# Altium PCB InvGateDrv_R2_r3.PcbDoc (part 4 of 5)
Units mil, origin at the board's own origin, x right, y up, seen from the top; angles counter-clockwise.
Board outline 6245 x 2850 mil, 4 copper layers (Top Layer, Power, Ground, Bottom Layer), stack 104.204 mil thick; 409 components, 181 nets, 1050 pads, 683 vias.
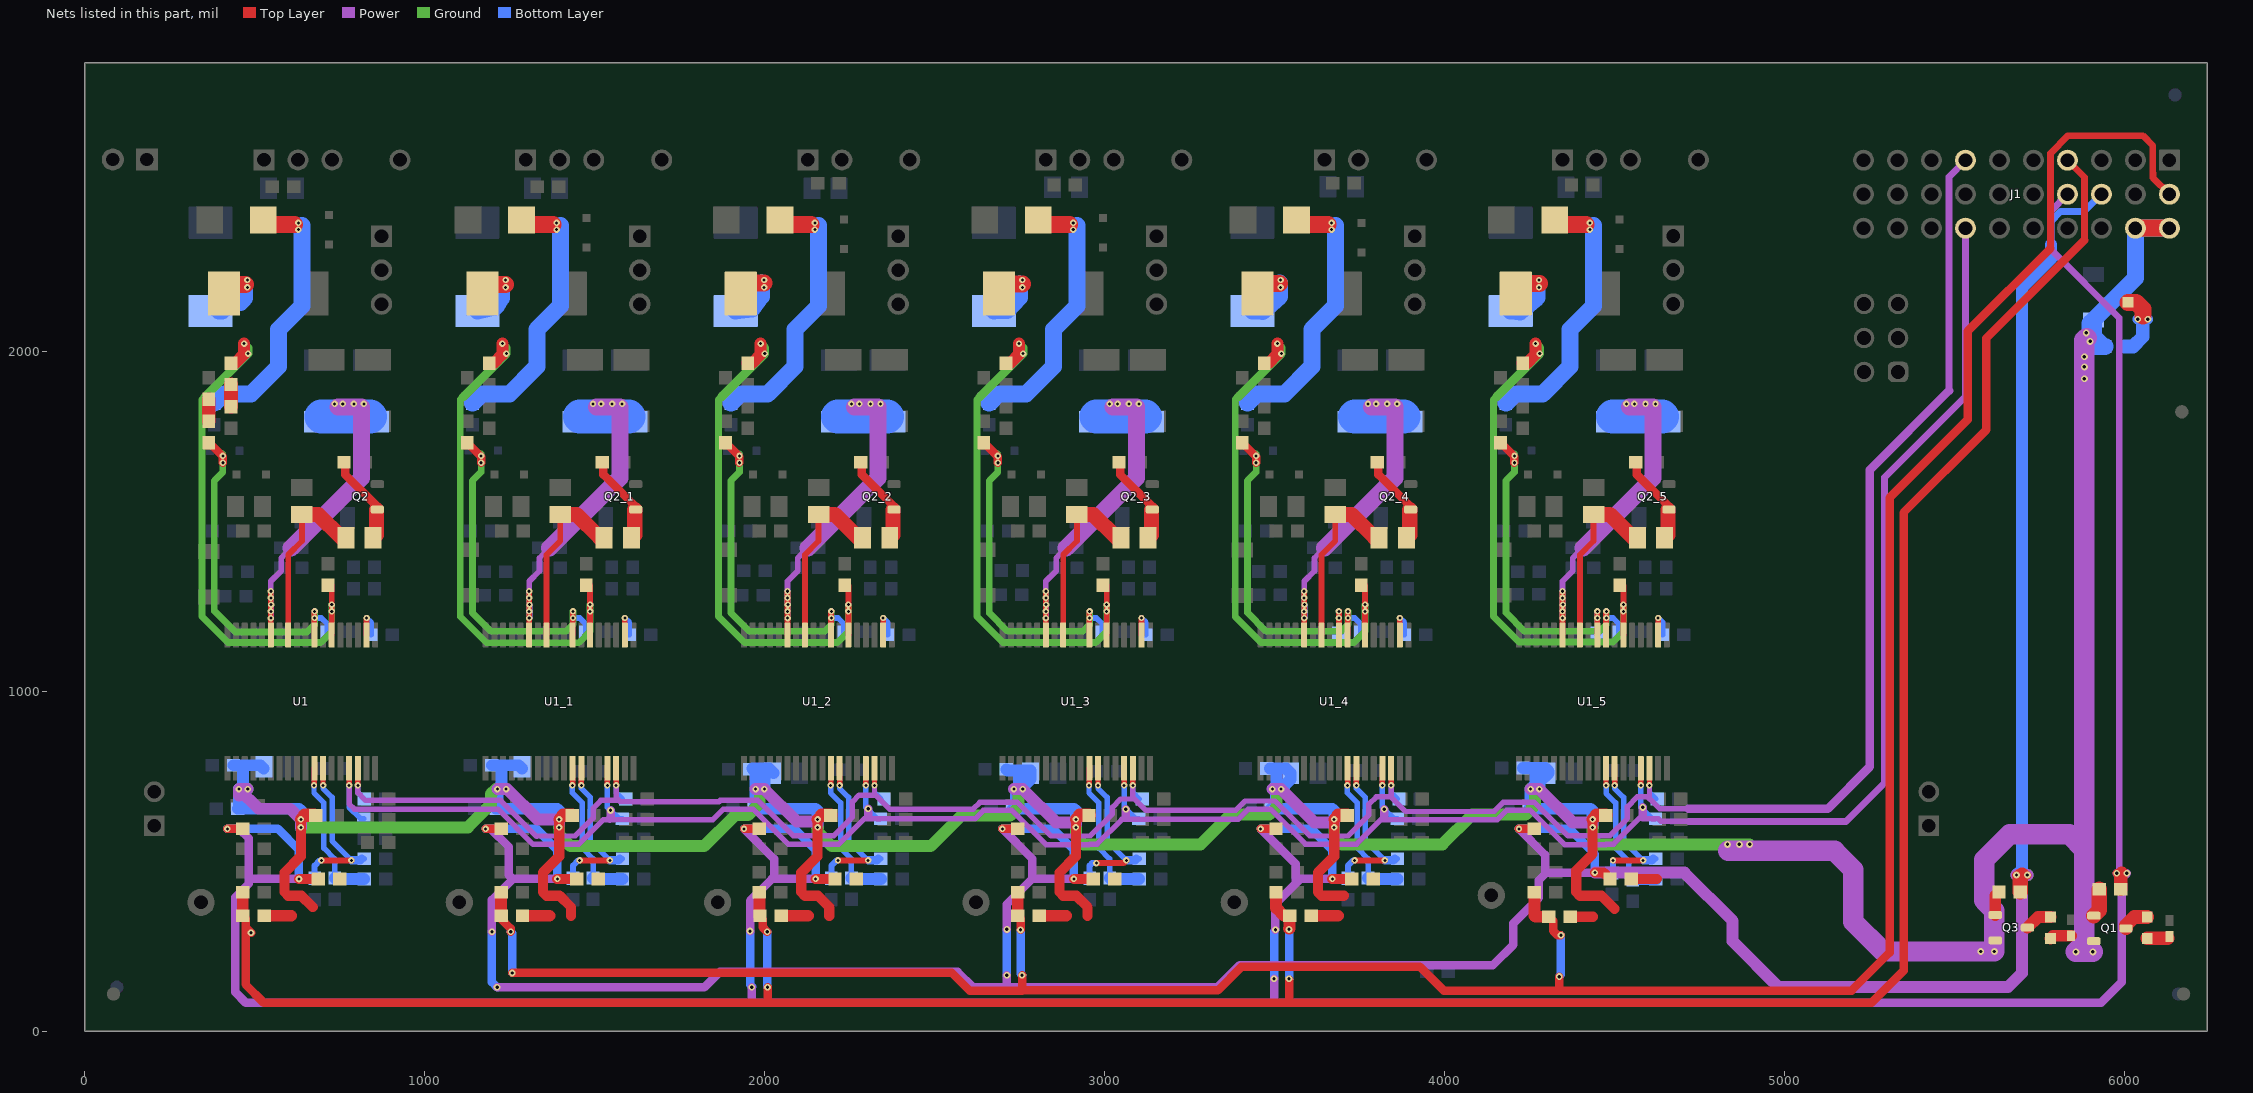
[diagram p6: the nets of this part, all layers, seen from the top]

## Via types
v1: diameter 19, hole 9, Top Layer to Bottom Layer, tented both sides, 617 vias
v2: diameter 20, hole 10, Top Layer to Bottom Layer, tented both sides, 66 vias

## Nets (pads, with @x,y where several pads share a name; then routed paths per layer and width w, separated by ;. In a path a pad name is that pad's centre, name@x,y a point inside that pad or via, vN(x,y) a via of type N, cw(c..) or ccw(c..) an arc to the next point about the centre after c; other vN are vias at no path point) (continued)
NetC17_4_1: C17_4.1 U1_4.27 | length 174.7
  Top Layer w17: U1_4.27@3690.16,1165.91 v1(3690.16,1235.79)
  Power w17: v1(3690.16,1216.1) v1(3690.16,1235.79)
  Ground w17: v1(3690.16,1216.1) v1(3690.16,1235.79)
  Bottom Layer w17: v1(3690.16,1235.79) v1(3690.16,1216.1) 3690.16,1178.7 C17_4.1@3696.06,1172.79
NetC17_5_1: C17_5.1 U1_5.27 | length 174.7
  Top Layer w17: U1_5.27@4450.15,1165.91 v1(4450.15,1216.11) v1(4450.15,1235.79)
  Power w17: v1(4450.15,1216.11) v1(4450.15,1235.79)
  Ground w17: v1(4450.15,1216.11) v1(4450.15,1235.79)
  Bottom Layer w17: v1(4450.15,1235.79) v1(4450.15,1216.11) 4450.15,1178.71 C17_5.1@4456.06,1172.8
NetC18_1: C18.1 R18.1 U1.26 | length 1077.1
  Top Layer w17: U1.26@675.75,1165.91 675.75,1234.8 v1(676.73,1235.79)
  Top Layer w25: R18.1@365.39,1732.09 406.57,1690.91 v1(406.57,1672.89)
  Ground w20: v1@406.57,1698.39 v1(406.57,1692.81) v1(406.57,1672.89) 406.57,1645.15 381.46,1620.03 381.46,1236.75 443.2,1175 654.33,1175 676.73,1197.4 v1(676.73,1216.1) v1(676.73,1235.79)
  Bottom Layer w17: v1(676.73,1235.79) v1(676.73,1216.1) 696.42,1216.1 714.13,1198.39 C18.1@714.13,1175.86 C18.1@714.13,1172.8
NetC18_1_1: C18_1.1 R18_1.1 U1_1.26 | length 1079.1
  Top Layer w17: U1_1.26@1435.74,1165.91 1435.74,1234.81 v1(1436.73,1235.79)
  Top Layer w25: R18_1.1@1125.39,1732.09 1166.57,1690.91 v1(1166.57,1672.89)
  Ground w20: v1@1166.57,1698.39 v1(1166.57,1692.81) v1(1166.57,1672.89) 1166.57,1645.15 1141.45,1620.04 1141.45,1230.49 1194.89,1177.05 1416.37,1177.05 1436.73,1197.4 v1(1436.73,1216.1) v1(1436.73,1235.79)
  Bottom Layer w17: v1(1436.73,1235.79) v1(1436.73,1216.1) 1456.41,1216.1 1474.13,1198.39 C18_1.1@1474.13,1175.87 C18_1.1@1474.13,1172.8
NetC18_2_1: C18_2.1 R18_2.1 U1_2.26 | length 1078.8
  Top Layer w17: U1_2.26@2195.75,1165.91 2195.75,1234.8 v1(2196.73,1235.79)
  Top Layer w25: R18_2.1@1885.39,1732.09 1926.57,1690.91 v1(1926.57,1672.89)
  Ground w20: v1@1926.57,1698.39 v1(1926.57,1692.81) v1(1926.57,1672.89) 1926.57,1645.15 1901.46,1620.03 1901.46,1230.94 1955.35,1177.05 2176.38,1177.05 2196.73,1197.4 v1(2196.73,1216.1) v1(2196.73,1235.79)
  Bottom Layer w17: v1(2196.73,1235.79) v1(2196.73,1216.1) 2216.42,1216.1 2234.13,1198.39 C18_2.1@2234.13,1175.86 C18_2.1@2234.13,1172.79
NetC18_3_1: C18_3.1 R18_3.1 U1_3.26 | length 1078.7
  Top Layer w17: U1_3.26@2955.75,1165.91 2955.75,1234.8 v1(2956.73,1235.79)
  Top Layer w25: R18_3.1@2645.39,1732.09 2686.57,1690.91 v1(2686.57,1672.89)
  Ground w20: v1@2686.57,1698.39 v1(2686.57,1692.81) v1(2686.57,1672.89) 2686.57,1645.15 2661.46,1620.03 2661.46,1231.08 2715.49,1177.05 2936.38,1177.05 2956.73,1197.4 v1(2956.73,1216.1) v1(2956.73,1235.79)
  Bottom Layer w17: v1(2956.73,1235.79) v1(2956.73,1216.1) 2976.42,1216.1 2994.13,1198.39 C18_3.1@2994.13,1175.86 C18_3.1@2994.13,1172.8
NetC18_4_1: C18_4.1 R18_4.1 U1_4.26 | length 1078.3
  Top Layer w17: U1_4.26@3715.75,1165.91 3715.75,1234.8 v1(3716.73,1235.79)
  Top Layer w25: R18_4.1@3405.39,1732.09 3446.57,1690.91 v1(3446.57,1672.89)
  Ground w20: v1@3446.57,1698.39 v1(3446.57,1692.81) v1(3446.57,1672.89) 3446.57,1645.15 3421.46,1620.03 3421.46,1231.77 3476.18,1177.05 3696.38,1177.05 3716.73,1197.4 v1(3716.73,1216.1) v1(3716.73,1235.79)
  Bottom Layer w17: v1(3716.73,1235.79) v1(3716.73,1216.1) 3736.42,1216.1 3754.13,1198.39 C18_4.1@3754.13,1175.86 C18_4.1@3754.13,1172.79
NetC18_5_1: C18_5.1 R18_5.1 U1_5.26 | length 1078.3
  Top Layer w17: U1_5.26@4475.74,1165.91 4475.74,1234.81 v1(4476.73,1235.79)
  Top Layer w25: R18_5.1@4165.39,1732.09 4206.57,1690.91 v1(4206.57,1672.89)
  Ground w20: v1@4206.57,1698.39 v1(4206.57,1692.81) v1(4206.57,1672.89) 4206.57,1645.16 4181.45,1620.04 4181.45,1231.77 4236.17,1177.05 4456.38,1177.05 4476.73,1197.41 v1(4476.73,1216.11) v1(4476.73,1235.79)
  Bottom Layer w17: v1(4476.73,1235.79) v1(4476.73,1216.11) 4496.41,1216.11 4514.13,1198.39 C18_5.1@4514.13,1175.87 C18_5.1@4514.13,1172.8
NetC19_1: C19.1 R21.1 U1.24 | length 1598.3
  Top Layer w17: C19.1@725.94,1312.56 726.93,1311.57 v1(726.93,1255.47) v1(726.93,1235.79) U1.24@726.93,1165.91
  Top Layer w35: R21.1@430.51,1966.1 443.46,1966.1 468.9,1991.54 v1(468.9,2023.19)
  Ground w20: 352.91,1865.71 351.69,1865.71 345,1859.02 345,1220.4 421.15,1144.25 694.84,1144.25 726.93,1176.34 v1(726.93,1235.79) v1(726.93,1255.47)
  Ground w25: 352.91,1865.71 v1(480.87,1993.66) 480.87,2011.22 v1(468.9,2023.19)
NetC19_1_1: C19_1.1 R21_1.1 U1_1.24 | length 1599.1
  Top Layer w17: C19_1.1@1485.94,1312.56 1486.92,1311.58 v1(1486.92,1255.47) v1(1486.92,1235.79) U1_1.24@1486.92,1165.91
  Top Layer w35: R21_1.1@1190.51,1966.1 1203.46,1966.1 1228.89,1991.54 v1(1228.89,2023.19)
  Ground w20: 1112.91,1865.71 1111.69,1865.71 1105,1859.02 1105,1220.4 1182.13,1143.27 1453.85,1143.27 1486.92,1176.34 v1(1486.92,1235.79) v1(1486.92,1255.47)
  Ground w25: 1112.91,1865.71 v1(1240.86,1993.66) 1240.86,2011.22 v1(1228.89,2023.19)
NetC19_2_1: C19_2.1 R21_2.1 U1_2.24 | length 1598.3
  Top Layer w17: C19_2.1@2245.94,1312.56 2246.93,1311.57 v1(2246.93,1255.47) v1(2246.93,1235.79) U1_2.24@2246.93,1165.91
  Top Layer w35: R21_2.1@1950.51,1966.1 1963.46,1966.1 1988.9,1991.54 v1(1988.9,2023.19)
  Ground w20: 1872.91,1865.71 1871.69,1865.71 1865,1859.02 1865,1220.4 1941.15,1144.25 2214.84,1144.25 2246.93,1176.34 v1(2246.93,1235.79) v1(2246.93,1255.47)
  Ground w25: 1872.91,1865.71 v1(2000.87,1993.66) 2000.87,2011.22 v1(1988.9,2023.19)
NetC19_3_1: C19_3.1 R21_3.1 U1_3.24 | length 1598.3
  Top Layer w17: C19_3.1@3005.94,1312.56 3006.93,1311.57 v1(3006.93,1255.47) v1(3006.93,1235.79) U1_3.24@3006.93,1165.91
  Top Layer w35: R21_3.1@2710.51,1966.1 2723.46,1966.1 2748.9,1991.54 v1(2748.9,2023.19)
  Ground w20: 2632.91,1865.71 2631.69,1865.71 2625,1859.02 2625,1220.4 2701.15,1144.25 2974.84,1144.25 3006.93,1176.34 v1(3006.93,1235.79) v1(3006.93,1255.47)
  Ground w25: 2632.91,1865.71 v1(2760.87,1993.66) 2760.87,2011.22 v1(2748.9,2023.19)
NetC19_4_1: C19_4.1 R21_4.1 U1_4.24 | length 1598.3
  Top Layer w17: C19_4.1@3765.94,1312.56 3766.93,1311.57 v1(3766.93,1255.47) v1(3766.93,1235.79) U1_4.24@3766.93,1165.91
  Top Layer w35: R21_4.1@3470.51,1966.1 3483.46,1966.1 3508.9,1991.54 v1(3508.9,2023.19)
  Ground w20: 3392.91,1865.71 3391.69,1865.71 3385,1859.02 3385,1220.4 3461.15,1144.25 3734.84,1144.25 3766.93,1176.34 v1(3766.93,1235.79) v1(3766.93,1255.47)
  Ground w25: 3392.91,1865.71 v1(3520.87,1993.66) 3520.87,2011.22 v1(3508.9,2023.19)
NetC19_5_1: C19_5.1 R21_5.1 U1_5.24 | length 1597.2
  Top Layer w17: C19_5.1@4525.94,1312.56 4526.93,1311.58 v1(4526.93,1255.48) v1(4526.93,1235.79) U1_5.24@4526.93,1165.91
  Top Layer w35: R21_5.1@4230.51,1966.11 4243.46,1966.11 4268.89,1991.54 v1(4268.89,2023.19)
  Ground w20: 4152.91,1865.71 4151.69,1865.71 4145,1859.02 4145,1220.4 4219.87,1145.53 4496.12,1145.53 4526.93,1176.34 v1(4526.93,1235.79) v1(4526.93,1255.48)
  Ground w25: 4152.91,1865.71 v1(4280.86,1993.67) 4280.86,2011.23 v1(4268.89,2023.19)
NetC25_1: C25.1 R17.2 U1.11 | length 436.4
  Top Layer w16: v1(674.76,723.98) 675.75,724.96 U1.11@675.75,774.17
  Bottom Layer w16: v1(674.76,723.98) 674.76,701.34 704.04,672.06 704.04,539.19 735.79,507.44 R17.2@735.79,451.34
  Bottom Layer w35: R17.2@735.79,451.34 738.74,448.39 C25.1@822.4,448.39
NetC25_1_1: C25_1.1 R17_1.2 U1_1.11 | length 436.4
  Top Layer w16: v1(1434.76,723.98) 1435.74,724.96 U1_1.11@1435.74,774.18
  Bottom Layer w16: v1(1434.76,723.98) 1434.76,701.34 1464.04,672.07 1464.04,539.19 1495.78,507.44 R17_1.2@1495.78,451.34
  Bottom Layer w35: R17_1.2@1495.78,451.34 1498.74,448.39 C25_1.1@1582.4,448.39
NetC25_2_1: C25_2.1 R17_2.2 U1_2.11 | length 436.4
  Top Layer w16: v1(2194.76,723.98) 2195.75,724.96 U1_2.11@2195.75,774.17
  Bottom Layer w16: v1(2194.76,723.98) 2194.76,701.34 2224.04,672.06 2224.04,539.19 2255.79,507.44 R17_2.2@2255.79,451.34
  Bottom Layer w35: R17_2.2@2255.79,451.34 2258.74,448.39 C25_2.1@2342.4,448.39
NetC25_3_1: C25_3.1 R17_3.2 U1_3.11 | length 436.4
  Top Layer w16: v1(2954.76,723.98) 2955.75,724.96 U1_3.11@2955.75,774.17
  Bottom Layer w16: v1(2954.76,723.98) 2954.76,701.34 2984.04,672.06 2984.04,539.19 3015.79,507.44 R17_3.2@3015.79,451.34
  Bottom Layer w35: R17_3.2@3015.79,451.34 3018.74,448.39 C25_3.1@3102.4,448.39
NetC25_4_1: C25_4.1 R17_4.2 U1_4.11 | length 436.4
  Top Layer w16: v1(3714.76,723.98) 3715.75,724.96 U1_4.11@3715.75,774.17
  Bottom Layer w16: v1(3714.76,723.98) 3714.76,701.34 3744.04,672.06 3744.04,539.19 3775.79,507.44 R17_4.2@3775.79,451.34
  Bottom Layer w35: R17_4.2@3775.79,451.34 3778.74,448.39 C25_4.1@3862.4,448.39
NetC25_5_1: C25_5.1 R17_5.2 U1_5.11 | length 412.6
  Top Layer w16: U1_5.11@4475.74,774.18 4475.74,724.97 4476,724.71 v1(4476,724)
  Bottom Layer w16: v1(4476,724) 4476,700.1 4504.04,672.07 4504.04,539.19 4543.35,499.88 4543.35,462.62 R17_5.2@4553.35,452.62
  Bottom Layer w35: R17_5.2@4563.5,448.39 C25_5.1@4622.4,448.39
NetC26_1: C26.1 R19.2 U1.12 | length 496.8
  Top Layer w16: v1(701.34,723.98) U1.12@701.34,774.17
  Top Layer w18: v1(696.42,503.24) v1(785,503.24)
  Bottom Layer w16: v1(701.34,723.98) 701.34,714.82 727.91,688.24 727.91,560.32 v1(785,503.24) ; C26.1@814.53,507.44 C26.1@822.4,507.44
  Bottom Layer w18: R19.2@676.73,450.35 676.73,487.76 692.21,503.24 v1(696.42,503.24)
  Bottom Layer w25: v1(785,503.24) 810.32,503.24 C26.1@814.53,507.44
NetC26_1_1: C26_1.1 R19_1.2 U1_1.12 | length 496.8
  Top Layer w16: v1(1461.33,723.98) U1_1.12@1461.33,774.18
  Top Layer w18: v1(1456.41,503.24) v1(1545,503.24)
  Bottom Layer w16: v1(1461.33,723.98) 1461.33,714.82 1487.91,688.25 1487.91,560.32 v1(1545,503.24) ; C26_1.1@1574.52,507.44 C26_1.1@1582.4,507.44
  Bottom Layer w18: R19_1.2@1436.73,450.36 1436.73,487.76 1452.21,503.24 v1(1456.41,503.24)
  Bottom Layer w25: v1(1545,503.24) 1570.32,503.24 C26_1.1@1574.52,507.44
NetC26_2_1: C26_2.1 R19_2.2 U1_2.12 | length 496.8
  Top Layer w16: v1(2221.34,723.98) U1_2.12@2221.34,774.17
  Top Layer w18: v1(2216.42,503.24) v1(2305,503.24)
  Bottom Layer w16: v1(2221.34,723.98) 2221.34,714.82 2247.91,688.24 2247.91,560.32 v1(2305,503.24) ; C26_2.1@2334.53,507.44 C26_2.1@2342.4,507.44
  Bottom Layer w18: R19_2.2@2196.73,450.35 2196.73,487.76 2212.21,503.24 v1(2216.42,503.24)
  Bottom Layer w25: v1(2305,503.24) 2330.32,503.24 C26_2.1@2334.53,507.44
NetC26_3_1: C26_3.1 R19_3.2 U1_3.12 | length 497.2
  Top Layer w16: v1(2981.34,723.98) U1_3.12@2981.34,774.17
  Top Layer w18: v1(2976.42,495) 3056.76,495 v1(3065,503.24)
  Bottom Layer w16: v1(2981.34,723.98) 2981.34,714.82 3007.91,688.24 3007.91,560.32 v1(3065,503.24) ; C26_3.1@3094.53,507.44 C26_3.1@3102.4,507.44
  Bottom Layer w18: R19_3.2@2956.73,450.35 2956.73,487.76 2964.49,495.51 2965,495 v1(2976.42,495)
  Bottom Layer w25: v1(3065,503.24) 3090.32,503.24 C26_3.1@3094.53,507.44
NetC26_4_1: C26_4.1 R19_4.2 U1_4.12 | length 496.8
  Top Layer w16: v1(3741.34,723.98) U1_4.12@3741.34,774.17
  Top Layer w18: v1(3736.42,503.24) v1(3825,503.24)
  Bottom Layer w16: v1(3741.34,723.98) 3741.34,714.82 3767.91,688.24 3767.91,560.32 v1(3825,503.24) ; C26_4.1@3854.53,507.44 C26_4.1@3862.4,507.44
  Bottom Layer w18: R19_4.2@3716.73,450.35 3716.73,487.76 3732.21,503.24 v1(3736.42,503.24)
  Bottom Layer w25: v1(3825,503.24) 3850.32,503.24 C26_4.1@3854.53,507.44
NetC26_5_1: C26_5.1 R19_5.2 U1_5.12 | length 461.4
  Top Layer w16: v1(4501.34,723.98) U1_5.12@4501.34,774.18
  Top Layer w18: v1(4496.41,503.24) v1(4585,503.24)
  Bottom Layer w16: v1(4501.34,723.98) 4501.34,714.82 4527.91,688.25 4527.91,560.33 v1(4585,503.24) ; C26_5.1@4614.52,507.45 C26_5.1@4622.4,507.45
  Bottom Layer w18: R19_5.2@4492.21,476.93 4496.41,481.14 v1(4496.41,503.24)
  Bottom Layer w25: v1(4585,503.24) 4610.32,503.24 C26_5.1@4614.52,507.45
NetC28_1: C28.1 U1.20 | length 104.7
  Top Layer w17: U1.20@829.29,1165.91 v1(829.29,1216.1)
  Bottom Layer w17: v1(829.29,1216.1) 842.09,1203.31 C28.1@842.09,1166.89
NetC28_1_1: C28_1.1 U1_1.20 | length 104.7
  Top Layer w17: U1_1.20@1589.29,1165.91 v1(1589.29,1216.1)
  Bottom Layer w17: v1(1589.29,1216.1) 1602.08,1203.31 C28_1.1@1602.08,1166.89
NetC28_2_1: C28_2.1 U1_2.20 | length 104.7
  Top Layer w17: U1_2.20@2349.29,1165.91 v1(2349.29,1216.1)
  Bottom Layer w17: v1(2349.29,1216.1) 2362.09,1203.31 C28_2.1@2362.09,1166.89
NetC28_3_1: C28_3.1 U1_3.20 | length 104.7
  Top Layer w17: U1_3.20@3109.29,1165.91 v1(3109.29,1216.1)
  Bottom Layer w17: v1(3109.29,1216.1) 3122.09,1203.31 C28_3.1@3122.09,1166.89
NetC28_4_1: C28_4.1 U1_4.20 | length 104.7
  Top Layer w17: U1_4.20@3869.29,1165.91 v1(3869.29,1216.1)
  Bottom Layer w17: v1(3869.29,1216.1) 3882.09,1203.31 C28_4.1@3882.09,1166.89
NetC28_5_1: C28_5.1 U1_5.20 | length 104.7
  Top Layer w17: U1_5.20@4629.29,1165.91 v1(4629.29,1216.11)
  Bottom Layer w17: v1(4629.29,1216.11) 4642.08,1203.31 C28_5.1@4642.08,1166.89
NetD1_1: D1.1 R3.2 | length 59.3
  Top Layer w40: D1.1@6068.35,273.5 R3.2@6127.65,273.5
NetD1_2: D1.2 Q1.3 | length 82.2
  Top Layer w40: Q1.3@6005.59,302.82 6005.59,312.24 6029.84,336.5 D1.2@6068.35,336.5
NetD2_2: D2.2 R27.1 | length 203.6
  Top Layer w50: D2.2@6011.5,2145 6035,2145 6055,2125 6055,2105
  Bottom Layer w30: v2(6040,2095) v2(6070,2095)
  Bottom Layer w40: R27.1@6001.5,2015 R27.1@6006.5,2015 6026.5,2015 6055,2043.5 6055,2080
NetD3_1_2: D3_1.2 R4_1.2 | length 774.6
  Top Layer w50: D3_1.2@1285.35,2387.36 1299.52,2373.19 1377.67,2373.19
  Bottom Layer w50: R4_1.2@1141.3,1847.99 1168.85,1875.55 1249.56,1875.55 1330.27,1956.26 1330.27,2065.36 1399.33,2134.41 1399.33,2370.2
  other v1: 1388.53,2358.82 1388.53,2378.51
NetD3_2: D3.2 R4.2 | length 774.6
  Top Layer w50: D3.2@525.35,2387.36 539.53,2373.19 617.68,2373.19
  Bottom Layer w50: R4.2@381.3,1847.99 408.86,1875.55 489.57,1875.55 570.28,1956.26 570.28,2065.35 639.33,2134.41 639.33,2370.2
  other v1: 628.53,2358.82 628.53,2378.5
NetD3_2_2: D3_2.2 R4_2.2 | length 774.6
  Top Layer w50: D3_2.2@2045.35,2387.36 2059.53,2373.19 2137.68,2373.19
  Bottom Layer w50: R4_2.2@1901.3,1847.99 1928.86,1875.55 2009.57,1875.55 2090.28,1956.26 2090.28,2065.35 2159.33,2134.41 2159.33,2370.2
  other v1: 2148.53,2358.82 2148.53,2378.5
NetD3_3_2: D3_3.2 R4_3.2 | length 774.6
  Top Layer w50: D3_3.2@2805.35,2387.36 2819.53,2373.19 2897.68,2373.19
  Bottom Layer w50: R4_3.2@2661.3,1847.99 2688.86,1875.55 2769.57,1875.55 2850.28,1956.26 2850.28,2065.35 2919.33,2134.41 2919.33,2370.2
  other v1: 2908.53,2358.82 2908.53,2378.5
NetD3_4_2: D3_4.2 R4_4.2 | length 774.6
  Top Layer w50: D3_4.2@3565.35,2387.36 3579.53,2373.19 3657.68,2373.19
  Bottom Layer w50: R4_4.2@3421.3,1847.99 3448.86,1875.55 3529.57,1875.55 3610.28,1956.26 3610.28,2065.35 3679.33,2134.41 3679.33,2370.2
  other v1: 3668.53,2358.82 3668.53,2378.5
NetD3_5_2: D3_5.2 R4_5.2 | length 774.6
  Top Layer w50: D3_5.2@4325.35,2387.37 4339.52,2373.19 4417.67,2373.19
  Bottom Layer w50: R4_5.2@4181.3,1848 4208.86,1875.56 4289.56,1875.56 4370.27,1956.26 4370.27,2065.36 4439.33,2134.41 4439.33,2370.2
  other v1: 4428.53,2358.82 4428.53,2378.51
NetD7_1: D7.1 D8.2 | length 213.9
  Top Layer w50: D7.1@408.29,2170.83 408.29,2182.89 422.28,2196.89 473.35,2196.89
  Bottom Layer w50: D8.2@395.35,2119.02 404.02,2119.02 430,2145 458.68,2145 470.75,2157.07 470.75,2196.89
  other v1: 478.74,2188.62 478.74,2210.55
NetD7_1_1: D7_1.1 D8_1.2 | length 214
  Top Layer w50: D7_1.1@1168.28,2170.83 1168.28,2182.9 1182.28,2196.89 v1@1238.74,2196.89
  Bottom Layer w50: D8_1.2@1155.35,2119.02 1210.5,2132.23 1225.74,2157.07 1225.74,2196.89
  other v1: 1238.74,2188.62 1238.74,2210.55
NetD7_2_1: D7_2.1 D8_2.2 | length 223.8
  Top Layer w50: D7_2.1@1928.29,2170.83 1928.29,2182.89 1947.28,2201.89 v1@1998.35,2201.89
  Bottom Layer w50: D8_2.2@1915.35,2119.02 1963.24,2125.68 1990.75,2162.07 1990.75,2201.89
  other v1: 1998.74,2188.62 1998.74,2210.55
NetD7_3_1: D7_3.1 D8_3.2 | length 219.8
  Top Layer w50: D7_3.1@2688.29,2170.83 2688.29,2182.89 2703.66,2198.27 2758.74,2198.27
  Bottom Layer w50: D8_3.2@2675.35,2119.02 2713.98,2120.24 2749.84,2158.44 2749.84,2198.27
  other v1: 2758.74,2188.62 2758.74,2210.55
NetD7_4_1: D7_4.1 D8_4.2 | length 223.9
  Top Layer w50: D7_4.1@3448.29,2170.83 3448.29,2182.89 3465.39,2200 3515.75,2200
  Bottom Layer w50: D8_4.2@3435.35,2119.02 3465.45,2117.27 3515.75,2162.07 v1@3515.75,2201.89
  other v1: 3518.74,2188.62 3518.74,2210.55
NetD7_5_1: D7_5.1 D8_5.2 | length 222.9
  Top Layer w50: D7_5.1@4208.28,2170.83 4208.28,2182.9 4225.39,2200 4279.88,2200
  Bottom Layer w50: D8_5.2@4195.35,2119.02 4222.19,2116.58 4272.45,2158.45 4272.45,2198.27
  other v1: 4278.74,2188.63 4278.74,2210.56
NetD13_1: D13.1 R30.2 | length 63.3
  Top Layer w35: D13.1@5783.35,273.5 5791.22,281.38 R30.2@5843.35,281.38
NetD13_2: D13.2 Q3.3 | length 80.8
  Top Layer w35: Q3.3@5715.59,305 5747.09,336.5 D13.2@5783.35,336.5
NetQ1_1: Q1.1 R1.2 | length 84.1
  Top Layer w45: Q1.1@5911.1,340.22 5926.85,355.97 R1.2@5926.85,417.82
NetQ2_1: Q2.1 R16.1 R20.2 | length 273.8
  Top Layer w25: R20.2@766.46,1678.7 766.46,1638.19 855.04,1549.61 ; Q2.1@855.04,1533.03 855.04,1549.61 ; Q2.1@861.18,1535 861.18,1543.46 855.04,1549.61
  Top Layer w45: R16.1@858.46,1460.2 Q2.1@858.46,1534.49
NetQ2_1_1: Q2_1.1 R16_1.1 R20_1.2 | length 273.8
  Top Layer w25: R20_1.2@1526.45,1678.7 1526.45,1638.19 1615.04,1549.61 ; Q2_1.1@1615.04,1533.03 1615.04,1549.61 ; Q2_1.1@1621.18,1535 1621.18,1543.47 1615.04,1549.61
  Top Layer w45: R16_1.1@1618.46,1460.2 Q2_1.1@1618.46,1534.49
NetQ2_2_1: Q2_2.1 R16_2.1 R20_2.2 | length 273.8
  Top Layer w25: R20_2.2@2286.46,1678.7 2286.46,1638.19 2375.04,1549.61 ; Q2_2.1@2375.04,1533.03 2375.04,1549.61 ; Q2_2.1@2381.18,1535 2381.18,1543.46 2375.04,1549.61
  Top Layer w45: R16_2.1@2378.46,1460.2 Q2_2.1@2378.46,1534.49
NetQ2_3_1: Q2_3.1 R16_3.1 R20_3.2 | length 273.8
  Top Layer w25: R20_3.2@3046.46,1678.7 3046.46,1638.19 3135.04,1549.61 ; Q2_3.1@3135.04,1533.03 3135.04,1549.61 ; Q2_3.1@3141.18,1535 3141.18,1543.46 3135.04,1549.61
  Top Layer w45: R16_3.1@3138.46,1460.2 Q2_3.1@3138.46,1534.49
NetQ2_4_1: Q2_4.1 R16_4.1 R20_4.2 | length 273.8
  Top Layer w25: R20_4.2@3806.46,1678.7 3806.46,1638.19 3895.04,1549.61 ; Q2_4.1@3895.04,1533.03 3895.04,1549.61 ; Q2_4.1@3901.18,1535 3901.18,1543.46 3895.04,1549.61
  Top Layer w45: R16_4.1@3898.46,1460.2 Q2_4.1@3898.46,1534.49
NetQ2_5_1: Q2_5.1 R16_5.1 R20_5.2 | length 273.8
  Top Layer w25: R20_5.2@4566.45,1678.71 4566.45,1638.19 4655.04,1549.61 ; Q2_5.1@4655.04,1533.04 4655.04,1549.61 ; Q2_5.1@4661.18,1535 4661.18,1543.47 4655.04,1549.61
  Top Layer w45: R16_5.1@4658.46,1460.2 Q2_5.1@4658.46,1534.49
NetQ3_1: Q3.1 R29.2 | length 72.1
  Top Layer w35: Q3.1@5621.1,342.4 5621.1,399.25 R29.2@5631.85,410
NetR15_1_2: R15_1.2 R16_1.2 U1_1.29 | length 529
  Top Layer w17: U1_1.29@1358.97,1165.91 1358.97,1402.13 1399.33,1442.48 R15_1.2@1399.33,1520.59
  Top Layer w45: R15_1.2@1399.33,1520.59 1447.2,1520.59 1515.47,1452.32 R16_1.2@1528.62,1452.32
NetR15_2: R15.2 R16.2 U1.29 | length 529
  Top Layer w17: U1.29@598.98,1165.91 598.98,1402.13 639.33,1442.48 R15.2@639.33,1520.59
  Top Layer w45: R15.2@639.33,1520.59 687.2,1520.59 755.47,1452.32 R16.2@768.62,1452.32
NetR15_2_2: R15_2.2 R16_2.2 U1_2.29 | length 529
  Top Layer w17: U1_2.29@2118.98,1165.91 2118.98,1402.13 2159.33,1442.48 R15_2.2@2159.33,1520.59
  Top Layer w45: R15_2.2@2159.33,1520.59 2207.2,1520.59 2275.47,1452.32 R16_2.2@2288.62,1452.32
NetR15_3_2: R15_3.2 R16_3.2 U1_3.29 | length 529
  Top Layer w17: U1_3.29@2878.98,1165.91 2878.98,1402.13 2919.33,1442.48 R15_3.2@2919.33,1520.59
  Top Layer w45: R15_3.2@2919.33,1520.59 2967.2,1520.59 3035.47,1452.32 R16_3.2@3048.62,1452.32
NetR15_4_2: R15_4.2 R16_4.2 U1_4.29 | length 529
  Top Layer w17: U1_4.29@3638.98,1165.91 3638.98,1402.13 3679.33,1442.48 R15_4.2@3679.33,1520.59
  Top Layer w45: R15_4.2@3679.33,1520.59 3727.2,1520.59 3795.47,1452.32 R16_4.2@3808.62,1452.32
NetR15_5_2: R15_5.2 R16_5.2 U1_5.29 | length 529
  Top Layer w17: U1_5.29@4398.97,1165.91 4398.97,1402.13 4439.33,1442.49 R15_5.2@4439.33,1520.6
  Top Layer w45: R15_5.2@4439.33,1520.6 4487.2,1520.6 4555.47,1452.33 R16_5.2@4568.62,1452.33
NetR18_2: R18.2 R22.1 | length 65
  Top Layer w40: R18.2@365.39,1795.08 R22.1@365.39,1860.04
NetR21_2: R21.2 R25.1 | length 65.9
  Top Layer w40: R25.1@430.51,1837.17 R21.2@430.51,1903.11
NetR26_1: R26.1 R28.1 U1.31 | length 1241
  Top Layer w17: U1.31@547.8,1165.91 v1(547.8,1235.79) v1(547.8,1275.16) v1@547.8,1293.86
  Power w17: v1@548.78,1216.1 v1(548.78,1255.47) 547.8,1256.46 v1(547.8,1275.16) 547.8,1293.86 547.8,1324.17 578.15,1354.53 578.15,1392.28 607.83,1421.97
  Power w50: 607.83,1421.97 814.37,1628.5 814.37,1826.34 804.53,1836.18 814.37,1836.18 745.47,1836.18
  Ground w17: v1@547.8,1293.86 v1(547.8,1275.16) 547.8,1256.46 v1(548.78,1255.47) v1@548.78,1216.1
  Bottom Layer w17: v1@547.8,1293.86 v1(547.8,1275.16) 547.8,1256.46 v1(548.78,1255.47) v1@548.78,1216.1
  Bottom Layer w100: R26.1@697.09,1809.53 759.29,1809.53 R28.1@840.12,1809.53
  other v1: 548,1216 547.8,1294.79 735.63,1846.02 759.29,1846.02 791.97,1846.02 821.46,1846.02
NetR26_1_1: R26_1.1 R28_1.1 U1_1.31 | length 1231.2
  Top Layer w17: U1_1.31@1307.79,1165.91 v1(1307.79,1235.79) v1(1307.79,1275.16) v1@1307.79,1293.86
  Power w17: v1@1308.78,1216.1 v1(1308.78,1255.47) 1307.79,1256.46 v1(1307.79,1275.16) 1307.79,1324.18 1338.15,1354.53 1338.15,1392.29 1367.83,1421.97
  Power w50: 1367.83,1421.97 1574.37,1628.51 1574.37,1826.34 1564.52,1836.18 ; 1505.47,1836.18 1574.37,1836.18
  Ground w17: v1@1307.79,1293.86 v1(1307.79,1275.16) 1307.79,1256.46 v1(1308.78,1255.47) v1@1308.78,1216.1
  Bottom Layer w17: v1@1307.79,1293.86 v1(1307.79,1275.16) 1307.79,1256.46 v1(1308.78,1255.47) v1@1308.78,1216.1
  Bottom Layer w100: R26_1.1@1457.08,1809.54 R28_1.1@1600.11,1809.54
  other v1: 1308,1216 1307.79,1294.79 1495.63,1846.03 1519.29,1846.03 1551.97,1846.03 1581.46,1846.03
NetR26_2_1: R26_2.1 R28_2.1 U1_2.31 | length 1241
  Top Layer w17: U1_2.31@2067.8,1165.91 v1(2067.8,1235.79) v1(2067.8,1275.16) v1@2067.8,1293.86
  Power w17: v1@2068.78,1216.1 v1(2068.78,1255.47) 2067.8,1256.46 v1(2067.8,1275.16) 2067.8,1293.86 2067.8,1324.17 2098.15,1354.53 2098.15,1392.28 2127.83,1421.97
  Power w50: 2127.83,1421.97 2334.37,1628.5 2334.37,1826.34 2324.53,1836.18 2334.37,1836.18 2265.47,1836.18
  Ground w17: v1@2067.8,1293.86 v1(2067.8,1275.16) 2067.8,1256.46 v1(2068.78,1255.47) v1@2068.78,1216.1
  Bottom Layer w17: v1@2067.8,1293.86 v1(2067.8,1275.16) 2067.8,1256.46 v1(2068.78,1255.47) v1@2068.78,1216.1
  Bottom Layer w100: R26_2.1@2217.09,1809.53 2279.29,1809.53 R28_2.1@2360.12,1809.53
  other v1: 2068,1215.99 2067.8,1294.79 2255.63,1846.02 2279.29,1846.02 2311.97,1846.02 2341.46,1846.02
NetR26_3_1: R26_3.1 R28_3.1 U1_3.31 | length 1241
  Top Layer w17: U1_3.31@2827.8,1165.91 v1(2827.8,1235.79) v1(2827.8,1275.16) v1@2827.8,1293.86
  Power w17: v1@2828.78,1216.1 v1(2828.78,1255.47) 2827.8,1256.46 v1(2827.8,1275.16) 2827.8,1293.86 2827.8,1324.17 2858.15,1354.53 2858.15,1392.28 2887.83,1421.97
  Power w50: 2887.83,1421.97 3094.37,1628.5 3094.37,1826.34 3084.53,1836.18 3094.37,1836.18 3025.47,1836.18
  Ground w17: v1@2827.8,1293.86 v1(2827.8,1275.16) 2827.8,1256.46 v1(2828.78,1255.47) v1@2828.78,1216.1
  Bottom Layer w17: v1@2827.8,1293.86 v1(2827.8,1275.16) 2827.8,1256.46 v1(2828.78,1255.47) v1@2828.78,1216.1
  Bottom Layer w100: R26_3.1@2977.09,1809.53 3039.29,1809.53 R28_3.1@3120.12,1809.53
  other v1: 2828,1216 2827.8,1294.79 3015.63,1846.02 3039.29,1846.02 3071.97,1846.02 3101.46,1846.02
NetR26_4_1: R26_4.1 R28_4.1 U1_4.31 | length 1231.2
  Top Layer w17: U1_4.31@3587.8,1165.91 v1(3587.8,1235.79) v1(3587.8,1275.16) v1@3587.8,1293.86
  Power w17: v1@3588.78,1216.1 v1(3588.78,1255.47) 3587.8,1256.46 v1(3587.8,1275.16) 3587.8,1324.17 3618.15,1354.53 3618.15,1392.28 3647.83,1421.97
  Power w50: 3647.83,1421.97 3854.37,1628.5 3854.37,1826.34 3844.53,1836.18 ; 3785.47,1836.18 3854.37,1836.18
  Ground w17: v1@3587.8,1293.86 v1(3587.8,1275.16) 3587.8,1256.46 v1(3588.78,1255.47) v1@3588.78,1216.1
  Bottom Layer w17: v1@3587.8,1293.86 v1(3587.8,1275.16) 3587.8,1256.46 v1(3588.78,1255.47) v1@3588.78,1216.1
  Bottom Layer w100: R26_4.1@3737.09,1809.53 R28_4.1@3880.12,1809.53
  other v1: 3588,1215.99 3587.8,1294.79 3775.63,1846.02 3799.29,1846.02 3831.97,1846.02 3861.46,1846.02
NetR26_5_1: R26_5.1 R28_5.1 U1_5.31 | length 1242.3
  Top Layer w17: U1_5.31@4347.79,1165.91 v1(4347.79,1235.79) v1(4347.79,1275.16) v1@4347.79,1293.86
  Power w17: v1(4348,1216) 4348,1254.7 v1(4348.78,1255.48) 4347.79,1256.46 v1(4347.79,1275.16) 4347.79,1293.86 4347.79,1324.18 4378.15,1354.53 4378.15,1392.29 4407.83,1421.97
  Power w50: 4407.83,1421.97 4614.37,1628.51 4614.37,1826.34 4604.52,1836.19 4614.37,1836.19 4545.47,1836.19
  Ground w17: v1@4347.79,1293.86 v1(4347.79,1275.16) 4347.79,1256.46 v1(4348.78,1255.48) 4348,1254.7 v1(4348,1216)
  Bottom Layer w17: v1@4347.79,1293.86 v1(4347.79,1275.16) 4347.79,1256.46 v1(4348.78,1255.48) 4348,1254.7 v1(4348,1216)
  Bottom Layer w100: R26_5.1@4497.08,1809.54 4559.29,1809.54 R28_5.1@4640.12,1809.54
  other v1: 4347.79,1294.79 4535.63,1846.03 4559.29,1846.03 4591.97,1846.03 4621.46,1846.03
nFLT1: J1.11 R1.1 R10.2 R10_2.2 R10_4.2 R13.1 R13_2.1 R13_4.1 | length 11614.2
  Top Layer w25: v1(419.84,596.02) R13.1@465.12,596.02 ; v1(1939.84,596.02) R13_2.1@1985.12,596.02 ; v1(3459.84,596.02) R13_4.1@3505.12,596.02 ; v2(5978.35,464.91) 5993.35,464.91
  Top Layer w30: v2(630.54,448.39) R10.2@687.56,448.39 ; v1(2150.54,448.39) R10_2.2@2207.56,448.39 ; v1(3670.54,448.39) R10_4.2@3727.56,448.39
  Top Layer w40: R1.1@5989.84,417.82 5989.84,461.4 5993.35,464.91
  Power w20: J1.11@5833.35,2462.88 5784.57,2414.1 5784.57,2300.43 5985.85,2099.15 5985.85,464.91 5985.85,457.41
  Power w25: v1(419.84,596.02) 454.8,596.02 483.35,567.48 483.35,449.37 ; v2(630.54,448.39) 484.33,448.39 483.35,449.37 ; v1(1939.84,596.02) 2028.35,507.52 2028.35,463.39 ; v2(1957.56,295) 1957.56,384.21 2021.73,448.39 v1(2150.54,448.39) ; v2(1962.45,130) 1962.45,88.32 1958.35,84.21 ; 3370,84.21 5932.56,84.21 5993.35,145 5993.35,449.91 ; v1(3459.84,596.02) 3563.11,492.76 3563.11,434.76 ; v2(3499.22,155) 3499.22,85.09 3498.35,84.21 1958.35,84.21 ; v2(3503.35,299.13) 3503.35,375 3563.11,434.76 ; 3623.35,448.39 3576.73,448.39 3563.11,434.76 ; 3628.35,448.39 v1(3670.54,448.39) ; 483.35,449.37 483.35,435 443.35,395 443.35,115 474.13,84.21 1958.35,84.21 ; 5993.35,449.91 v2(6008.35,464.91) 5985.85,464.91 v2(5978.35,464.91) 5985.85,457.41 5993.35,449.91
  Bottom Layer w25: v1(419.84,596.02) 568.46,596.02 630.54,533.95 v2(630.54,448.39) ; v1(1939.84,596.02) 2088.46,596.02 2150.54,533.95 v1(2150.54,448.39) ; v2(1957.56,295) 1957.56,137.66 1963.84,131.39 v2(1962.45,130) ; v1(3459.84,596.02) 3608.46,596.02 3670.54,533.95 v1(3670.54,448.39) ; v2(3499.22,155) 3499.22,295 v2(3503.35,299.13)
nFLT1_1: J1.8 R10_1.2 R10_3.2 R10_5.2 R13_1.1 R13_3.1 R13_5.1 R29.1 | length 10250.3
  Top Layer w25: v1(1179.84,596.03) R13_1.1@1225.11,596.03 ; v1(2699.84,596.02) R13_3.1@2745.12,596.02 ; v1(4219.84,596.03) R13_5.1@4265.12,596.03 ; v2(5683.35,460) 5699.47,460 v2(5715.59,460)
  Top Layer w30: v1(1390.54,448.39) R10_1.2@1447.55,448.39 ; v1(2910.54,448.39) R10_3.2@2967.56,448.39 ; v1(4443.35,467.09) 4468.86,467.09 R10_5.2@4487.56,448.39
  Top Layer w45: R29.1@5694.84,410 5694.84,455.37 5699.47,460
  Power w25: v1(1179.84,596.03) 1194.99,596.03 1248.35,542.67 1248.35,460.04 1260,448.39 ; v2(1198.35,292.82) 1198.35,386.74 1260,448.39 ; v2(1213.35,130) 1823.35,130 1868.35,175 2568.35,175 2613.35,130 2713.35,130 ; v1(1390.54,448.39) 1260,448.39 ; v1(2699.84,596.02) 2787.36,508.5 2787.36,448.39 ; v2(2713.35,165) 2713.35,130 ; v2(2713.35,300) 2713.35,374.37 2787.36,448.39 ; v1(2910.54,448.39) 2787.36,448.39 ; v1(4219.84,596.03) 4296.61,519.26 4296.61,470 4299.52,467.09 4300.43,467.09 ; v1(4443.35,467.09) 4300.43,467.09 ; 2713.35,130 3333.35,130 3398.35,195 4143.35,195 4203.35,255 4203.35,318.23 4278.35,393.23 4278.35,445 4300.43,467.09
  Power w35: v1(4443.35,467.09) 4706.26,467.09 4848.35,325 4848.35,265 4983.35,130 5658.35,130 5699.47,171.12 5699.47,460 ; v2(5683.35,460) 5699.47,460 ; v2(5715.59,460) 5699.47,460
  Bottom Layer w20: 5784.57,2315 5784.57,2383.09 5813.14,2411.66 5882.13,2411.66 J1.8@5933.35,2462.88
  Bottom Layer w25: v1(1179.84,596.03) 1328.46,596.03 1390.54,533.95 v1(1390.54,448.39) ; v2(1198.35,292.82) 1198.35,145 v2(1213.35,130) ; v1(2699.84,596.02) 2848.46,596.02 2910.54,533.95 v1(2910.54,448.39) ; v2(2713.35,165) v2(2713.35,300) ; v1(4219.84,596.03) 4368.46,596.03 4443.35,521.14 v1(4443.35,467.09)
  Bottom Layer w35: v2(5715.59,460) v2(5683.35,460) 5699.47,476.12 5699.47,2186.47 5784.57,2271.57 5784.57,2315
nFLT2/DOUT: J1.10 R11.1 R11_2.1 R11_4.1 R14.1 R14_2.1 R14_4.1 | length 8544.6
  Top Layer w20: J1.10@5833.35,2562.88 5883.35,2512.88 5883.35,2328.07
  Top Layer w25: R11.1@465.12,340.12 473.35,331.89 473.35,306.22 ; v2(489.57,290) 473.35,306.22 ; R11_2.1@1985.12,340.12 1994.96,330.28 1994.96,306.21 v2(2008.35,292.82) ; v2(2008.97,130) 2008.97,84.84 2008.35,84.21 ; v2@3543.35,152.28 3543.35,84.21 ; 5883.35,2328.07 5595,2039.72 5595,1770 5351.46,1526.46 5351.46,178.54 5257.14,84.21 3543.35,84.21 ; 473.35,306.22 473.35,138.03 527.16,84.21 2008.35,84.21 ; 2008.35,84.21 3543.35,84.21
  Top Layer w35: R11.1@465.12,340.12 R14.1@465.12,409.02 ; R11_2.1@1985.12,340.12 R14_2.1@1985.12,409.02 ; R14_4.1@3505.12,409.02 3505.12,363.23 3528.11,340.24 R11_4.1@3545.12,340.24 3545.12,302.87 v2@3543.35,302.87
  Bottom Layer w25: v2(2008.35,292.82) 2008.35,130.63 v2(2008.97,130) ; v2(3543.35,155) v2(3543.35,300)
nFLT2/DOUT_1: J1.2 R11_1.1 R11_3.1 R11_5.1 R14_1.1 R14_3.1 R14_5.1 | length 8121
  Top Layer w20: 5783.35,2303.35 5783.35,2583.35 5835,2635 6055,2635 6084.57,2605.43 6084.57,2525.23 6085,2524.79 6085,2511.23 J1.2@6133.35,2462.88
  Top Layer w25: R11_1.1@1225.11,340.12 1225.11,331.19 1253.35,302.96 v2(1253.35,292.82) ; v2(1257.75,171.79) 2551.55,171.79 2603.35,120 2758.35,120 2757.75,120.59 v2(2757.75,165) ; R11_3.1@2745.12,340.12 2753.35,331.89 v2(2753.35,298.46) ; 2758.35,120.59 3333.94,120.59 3403.35,190 3928.35,190 3998.35,120 4338.35,120 ; R11_5.1@4307.91,337.17 4320.23,324.85 4320.23,295.93 4333.35,282.82 v2(4343.35,282.82) ; v2(4338.35,161.15) 4338.35,120 ; 5783.35,2303.35 5540,2060 5540,1800 5310,1570 5310,231.65 5198.35,120 4338.35,120
  Top Layer w35: R11_1.1@1225.11,340.12 R14_1.1@1225.11,409.02 ; R11_3.1@2745.12,340.12 R14_3.1@2745.12,409.02 ; R14_5.1@4265.12,409.02 4265.12,340.12 4268.07,337.17 R11_5.1@4307.91,337.17
  Bottom Layer w25: v2(1253.35,292.82) 1257.75,288.41 v2(1257.75,171.79) ; v2(2753.35,298.46) 2753.35,169.41 v2(2757.75,165) ; v2(4338.35,161.15) 4343.35,166.15 v2(4343.35,282.82)
SDI: C22.1 C22_1.1 C22_2.1 C22_3.1 C22_4.1 C22_5.1 J1.21 U1.15 U1_1.15 U1_2.15 U1_3.15 U1_4.15 U1_5.15 | length 7937.2
  Top Layer w16: v1(778.14,723.98) U1.15@778.11,774.17 ; v1(1538.14,723.98) U1_1.15@1538.11,774.18 ; v1(2298.14,723.98) U1_2.15@2298.11,774.17 ; v1(3058.14,723.98) U1_3.15@3058.11,774.17 ; v1(3818.14,723.98) U1_4.15@3818.11,774.17 ; v1(4578.14,723.98) U1_5.15@4578.11,774.18
  Power w16: v1(778.14,723.98) 778.14,669.3 793.57,653.87 1215.72,653.87 1319.59,550 1435.65,550 1436.64,550.99 1454.33,550.99 1526.37,623.02 1847.97,623.02 1878.82,653.87 1966.62,653.87 2069.35,551.14 2219.22,551.14 2293.08,625 2618.88,625 2643.88,650 2728.35,650 2829.47,548.87 2954.53,548.87 2956.64,550.98 2978.72,550.98 3051.32,623.58 3393.6,623.58 3423.89,653.87 3488.24,653.87 3591.13,550.98 3741.93,550.98 3813.97,623.02 ; 3823.35,632.4 3813.97,623.02 ; 4577.57,630 4498.56,550.99 4476.64,550.99 4474.52,548.87 4354.47,548.87 4253.35,650 4183.35,650 4156.37,623.02 3813.97,623.02 ; 4584.12,625.56 4629.44,625.56 4637.22,617.78 4718.35,617.78
  Power w20: 4718.35,617.78 5181.55,617.78 5295,731.23 5295,1630 5533.35,1868.35 J1.21@5533.35,2362.88
  Power w25: 1545,626.05 1547.12,628.18 v2(1547.12,650) ; 2305,630 v2(2305,655) ; 3063.35,630 v2(3063.35,653.78) ; 3823.35,632.4 v2(3823.35,653.78) ; 4584.12,630 v2(4584.12,658.99)
  Bottom Layer w16: v1(778.14,723.98) 778.14,658.98 811.57,625.55 C22.1@821.42,625.55 ; v1(1538.14,723.98) 1538.14,658.99 v2(1547.12,650) 1571.57,625.55 C22_1.1@1581.41,625.55 ; v1(2298.14,723.98) 2298.14,658.98 2331.57,625.55 C22_2.1@2341.42,625.55 ; v1(3058.14,723.98) 3058.14,658.98 v2(3063.35,653.78) 3091.57,625.55 C22_3.1@3101.42,625.55 ; v1(3818.14,723.98) 3818.14,658.98 v2(3823.35,653.78) 3851.57,625.55 C22_4.1@3861.42,625.55 ; v1(4578.14,723.98) 4578.14,658.99 4611.57,625.56 C22_5.1@4621.41,625.56
SDO: C23.1 C23_1.1 C23_2.1 C23_3.1 C23_4.1 C23_5.1 J1.19 U1.16 U1_1.16 U1_2.16 U1_3.16 U1_4.16 U1_5.16 | length 7844.4
  Top Layer w16: v1(803.7,723.98) U1.16@803.7,774.17 ; v1(1563.7,723.98) U1_1.16@1563.7,774.18 ; v1(2323.7,723.98) U1_2.16@2323.7,774.17 ; v1(3083.7,723.98) U1_3.16@3083.7,774.17 ; v1(3843.7,723.98) U1_4.16@3843.7,774.17 ; v1(4603.7,723.98) U1_5.16@4603.7,774.18
  Power w16: v1(803.7,723.98) 803.7,702.32 826.61,679.42 1223.94,679.42 1329.48,573.87 1330.47,574.86 1443.21,574.86 1495.78,627.44 1495.78,656.38 1518.82,679.42 1571.76,679.42 ; v1(1563.7,723.98) 1563.7,687.48 1571.76,679.42 ; v1(2323.7,723.98) 2323.7,698.54 2327.24,695 ; v1(3083.7,723.98) 3083.7,688.54 3088.62,683.62 ; v1(3843.7,723.98) 3843.7,690.43 3843.27,690 ; 4598.43,690 4567.52,690 4538.35,660.83 4538.35,626.82 4486.53,575 4364.35,575 4265.47,673.87 4173.46,673.87 4146.48,646.9 3886.37,646.9 3843.27,690 ; v1(4603.7,723.98) 4603.7,684.94 4603.59,684.84 4633.35,655.08 4718.35,655.08 ; 1571.76,679.42 1576.05,675.13 1866.31,675.13 1870.6,679.42 1980.46,679.42 2084.87,575.02 2203.36,575.02 2258.35,630 2258.35,675 2278.35,695 2327.24,695 ; 2327.24,695 2368.47,653.78 2613.89,653.78 2633.99,673.87 2744.47,673.87 2843.49,574.86 2958.2,574.86 3023.35,640 3023.35,659.08 3047.89,683.62 3088.62,683.62 ; 3088.62,683.62 3122.24,650 3386.25,650 3414,677.75 3501.62,677.75 3604.51,574.86 3716.35,574.86 3778.35,636.85 3778.35,668.34 3800.01,690 3843.27,690
  Power w20: 5485,1885 5485,2342.25 5484.57,2342.68 5484.57,2514.1 J1.19@5533.35,2562.88
  Power w25: 4718.35,655.08 5128.43,655.08 5251.67,778.33 5251.67,1651.67 5485,1885
  Bottom Layer w16: v1(803.7,723.98) 803.76,723.92 803.76,702.27 C23.1@822.4,683.62 ; v1(1563.7,723.98) 1563.75,723.92 1563.75,702.27 C23_1.1@1582.4,683.62 ; v1(2323.7,723.98) 2323.76,723.92 2323.76,702.27 C23_2.1@2342.4,683.62 ; v1(3083.7,723.98) 3083.76,723.92 3083.76,702.27 C23_3.1@3102.4,683.62 ; v1(3843.7,723.98) 3843.76,723.92 3843.76,702.27 C23_4.1@3862.4,683.62 ; v1(4603.7,723.98) 4603.76,723.92 4603.76,702.27 C23_5.1@4622.4,683.63
VCC1: C1.1 C6.1 C6_1.1 C6_2.1 C6_3.1 C6_4.1 C6_5.1 C7.1 C7_1.1 C7_2.1 C7_3.1 C7_4.1 C7_5.1 J1.3 J1.6 Q1.2 Q3.2 R8.1 R8_1.1 R8_2.1 R8_3.1 R8_4.1 R8_5.1 R9.2 R9_1.2 R9_2.2 R9_3.2 R9_4.2 R9_5.2 R10.1 R10_1.1 R10_2.1 R10_3.1 R10_4.1 R10_5.1 R11.2 R11_1.2 R11_2.2 R11_3.2 R11_4.2 R11_5.2 R27.2 | length 16115.8
  Top Layer w30: v1(636.18,623.58) v1(636.18,600) 636.18,515.12 588.15,467.09 588.15,410 598.98,399.17 637.36,399.17 670.83,365.71 ; v1(1396.18,623.58) v1(1396.18,600) 1396.18,515.12 1348.15,467.09 1348.15,410 1358.97,399.18 1397.36,399.18 1430.82,365.71 1430.82,340.12 ; v1(2156.18,623.58) v1(2156.18,600) 2156.18,515.12 2108.15,467.09 2108.15,410 2118.98,399.17 2157.36,399.17 2190.83,365.71 2190.83,340.12 ; v1(2916.18,623.58) v1(2916.18,600) 2916.18,515.12 2868.15,467.09 2868.15,410 2878.98,399.17 2917.36,399.17 2950.83,365.71 2950.83,340.12 ; v1(3676.18,623.58) v1(3676.18,600) 3676.18,515.12 3628.15,467.09 3628.15,410 3638.98,399.17 3704.17,399.17 ; R11_5.2@4370.9,337.17 4371.03,337.29 4437.83,337.29 ; v1(4436.18,623.59) v1(4436.18,600) 4436.18,521.39 4388.15,473.36 4388.15,410 4398.97,399.18 4462.66,399.18 4500.82,361.02 ; R10_5.1@4550.55,448.39 4625.35,448.39
  Top Layer w35: R11.2@528.11,340.12 607.83,340.12 ; v1(636.18,623.58) 647.99,635.39 ; R11_1.2@1288.11,340.12 1367.83,340.12 ; v1(1396.18,623.58) 1407.99,635.4 ; R11_2.2@2048.11,340.12 2127.83,340.12 ; v1(2156.18,623.58) 2167.99,635.39 ; R11_3.2@2808.11,340.12 2887.83,340.12 ; v1(2916.18,623.58) 2927.99,635.39 ; R11_4.2@3608.11,340.24 3687.83,340.24 ; v1(3676.18,623.58) 3687.99,635.39 ; v1(4436.18,623.59) 4447.99,635.4
  Top Layer w40: 647.99,635.39 R9.2@674.76,635.39 ; 1407.99,635.4 R9_1.2@1434.76,635.4 ; 2167.99,635.39 R9_2.2@2194.76,635.39 ; 2927.99,635.39 R9_3.2@2954.76,635.39 ; 3687.99,635.39 R9_4.2@3714.76,635.39 ; 4447.99,635.4 R9_5.2@4474.76,635.4
  Top Layer w50: J1.6@6033.35,2362.88 J1.3@6133.35,2362.88
  Power w20: v2(5578.35,235) 5598.35,255
  Power w35: 454.02,693.73 v1(454.02,712.95) ; v1(479.88,712.95) v1(454.02,712.95) ; v1(636.18,600) v1@636.18,623.02 ; v1(1214.02,712.95) v1(1239.88,712.95) 1242.95,712.95 1332.32,623.58 1390.54,623.58 v1@1396.18,617.95 ; 1396.18,610 v1@1396.18,617.95 ; v1(1396.18,623.58) v1@1396.18,617.95 ; v1(1974.02,712.95) v1(1999.88,712.95) 2094.89,617.95 2151.1,617.95 v1@2156.18,623.02 ; v1@2155.62,623.58 v1@2156.18,623.02 ; 2156.18,610 v1@2156.18,623.02 ; v1(2156.18,623.58) v1@2156.18,623.02 ; v1(2734.02,712.95) v1(2759.88,712.95) 2857.83,615 2908.16,615 v1@2916.18,623.02 ; v1@2915.62,623.58 v1@2916.18,623.02 ; 2916.18,610 v1@2916.18,623.02 ; v1(2916.18,623.58) v1@2916.18,623.02 ; v1(3494.02,712.95) v1(3519.88,712.95) 3617.83,615 3668.16,615 v1@3676.18,623.02 ; v1@3675.62,623.58 v1@3676.18,623.02 ; 3676.18,610 v1@3676.18,623.02 ; v1(3676.18,623.58) v1@3676.18,623.02 ; v1(4254.02,712.96) v1(4279.88,712.96) 4377.84,615 4428.14,615 v1@4436.18,623.03 ; v1@4435.62,623.59 v1@4436.18,623.03 ; 4436.18,610 v1@4436.18,623.03 ; v1(4436.18,623.59) v1@4436.18,623.03 ; v1(454.02,712.95) 511.9,655.08 604.68,655.08 v1(636.18,623.58) ; v1@636.18,623.02 635.62,623.58 v1(636.18,623.58) ; v1@636.18,623.02 v1(636.18,623.58)
  Power w50: J1.6@6033.35,2362.88 J1.3@6133.35,2362.88
  Power w60: 4834.86,531.12 5148.35,531.12 ; 5148.35,530 5203.35,475 5203.35,322.76 5291.1,235 v2(5578.35,235) v2(5618.35,235) 5618.35,355 5588.35,385 5588.35,505 5663.35,580 5838.35,580 5883.35,535 ; 5890,2040 5883.35,2033.35 v2(5883.35,1985) v2(5883.35,1955) v2(5883.35,1920) 5883.35,535 ; v2(5908.35,233.92) v2(5858.35,233.92) 5883.35,258.92 5883.35,535
  Ground w35: v1(636.18,623.58) v1(636.18,600) 1127.46,600 1195.24,667.78 1195.24,698.79 1209.41,712.95 v1(1214.02,712.95) 1228.35,712.95 ; v1(1396.18,623.58) v1(1396.18,600) 1396.18,578.15 1429.32,545 1822.22,545 1913.59,636.38 1951.65,636.38 1986.12,670.84 1986.12,708.59 ; v1(2156.18,623.58) v1(2156.18,600) 2156.18,587.17 2198.35,545 2488.88,545 2578.88,635 2722.45,635 2747.1,659.65 2747.1,710 ; v1(2916.18,623.58) v1(2916.18,600) 2916.18,572.61 2938.79,550 3283.1,550 3370.82,637.72 3485.13,637.72 3507.05,659.64 3507.05,709.95 ; v1(3676.18,623.58) v1(3676.18,600) 3676.18,573.15 3699.33,550 3994.51,550 4082.24,637.73 4239.16,637.73 4266.95,665.51 4266.95,708.59 ; v1(4436.18,623.59) v1(4436.18,600) 4436.18,567.3 4453.48,550 v2(4833.35,550) v2(4868.35,550) v2(4898.35,550)
  Ground w50: J1.6@6033.35,2362.88 J1.3@6133.35,2362.88
  Bottom Layer w35: C7.1@437.95,783.03 466.44,783.03 ; v1(454.02,712.95) v1@454.22,712.95 ; v1(479.88,712.95) v1@454.22,712.95 ; R8.1@527.09,773.19 517.24,783.03 466.44,783.03 ; v1(636.18,600) v1(636.18,623.58) 636.18,649.44 630.54,655.08 C6.1@450.35,655.08 454.22,658.94 v1@454.22,712.95 ; C7_1.1@1197.95,783.03 1226.43,783.03 ; v1(1214.02,712.95) v1@1214.21,712.95 ; v1(1239.88,712.95) v1@1214.21,712.95 ; R8_1.1@1287.08,773.19 1277.24,783.03 1226.43,783.03 ; v1(1396.18,600) v1(1396.18,623.58) 1396.18,649.44 1390.54,655.08 C6_1.1@1210.35,655.08 1214.21,658.94 v1@1214.21,712.95 ; 1986.44,725.17 v1@1974.22,712.95 ; R8_2.1@2026.94,760 R8_2.1@2013.75,773.19 ; v1(2156.18,600) v1(2156.18,623.58) 2156.18,649.44 2150.54,655.08 C6_2.1@1970.35,655.08 1974.22,658.94 v1@1974.22,712.95 ; C7_3.1@2711.73,770.91 2715.35,767.28 2748.35,767.28 ; 2746.88,725.78 2748.35,727.28 2748.35,767.28 ; v1(2759.88,712.95) v1@2754.09,712.95 ; v1(2916.18,600) v1(2916.18,623.58) 2916.18,649.44 2910.54,655.08 C6_3.1@2730.35,655.08 2740,664.72 2740,712.95 v1@2754.09,712.95 ; C7_4.1@3487.79,773.19 3506.44,773.19 ; 3506.44,725.17 3506.44,773.19 ; v1(3676.18,600) v1(3676.18,623.58) 3676.18,649.44 3670.54,655.08 C6_4.1@3490.35,655.08 3505,669.72 3505,704.29 3496.34,712.95 v1(3519.88,712.95) 3548.35,741.42 R8_4.1@3548.35,760 3535.15,773.19 3506.44,773.19 ; C7_5.1@4231.72,775 4268.35,775 ; 4266.44,725.18 v1@4254.21,712.96 ; R8_5.1@4306.93,760 4279.88,732.94 v1(4279.88,712.96) v1@4254.21,712.96 ; R8_5.1@4306.93,765 4296.93,775 4268.35,775 ; v1(4436.18,600) v1(4436.18,623.59) 4436.18,649.45 4430.54,655.08 C6_5.1@4250.35,655.08 4254.21,658.95 v1@4254.21,712.96 ; v1@454.22,712.95 466.44,725.17 466.44,783.03 ; v1@1214.21,712.95 1226.43,725.18 1226.43,783.03 ; v1@1974.22,712.95 v1(1974.02,712.95) 1974.02,764.01 1964.84,773.19 R8_2.1@2013.75,773.19 ; v1@1974.22,712.95 v1(1999.88,712.95) 1999.88,759.32 R8_2.1@2013.75,773.19 ; 2748.35,767.28 2783.35,767.28 R8_3.1@2783.35,760 2783.35,742.21 v1@2754.09,712.95 ; v1@4254.21,712.96 v1(4254.02,712.96) 4268.35,727.28 4268.35,775
  Bottom Layer w50: v2(5883.35,1920) v2(5883.35,1955) v2(5883.35,1985) 5883.35,2033.35 ; R27.2@5943.5,2015 R27.2@5938.5,2015 ; J1.6@6033.35,2362.88 6033.35,2216.42 C1.1@5910,2093.07 ; 5883.35,2033.35 5901.75,2051.75 ; 5883.35,2033.35 5901.69,2015 R27.2@5938.5,2015 ; 5901.75,2051.75 R27.2@5938.5,2015 ; 5901.75,2051.75 5910,2060 C1.1@5910,2093.07 ; 5901.75,2051.75 5900,2053.5 5900,2083.07 C1.1@5910,2093.07
  other v2: 5900,2030 5888.52,2055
